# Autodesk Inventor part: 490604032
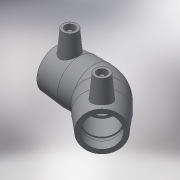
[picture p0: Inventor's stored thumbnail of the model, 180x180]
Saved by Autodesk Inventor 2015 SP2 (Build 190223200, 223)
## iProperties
Created: 2017-06
Part Number: 490604032
Material: Generic
Description: PLASSON 45° ELBOW 32
Document SubType Name: Modeling
Designer: KIM
Mass: 55.0731 g
Surface Area: 148.067 cm^2
Volume: 55.0731 cm^3
Density: 1 g/cm^3
Appearance: Default
Author: KIM
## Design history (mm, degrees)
derived "490604.ipt"
feature "Solid1::490604.ipt"
tag "TaggingFeature1"
body "Solid1"
other parameters: "d2" = 45, "d4" = 23.75, "d5" = 40.5, "d8" = 168 deg, "d10" = 15.6, "d11" = 5.2, "d14" = 17.6296, "d18" = 32, "d19" = 3.52592, "d20" = 168 deg, "d22" = 41.4, "d23" = 45, "d24" = 40.158, "d29" = 43, "d30" = 15, "d31" = 33.25, "d34" = 5 deg, "d35" = 12, "d39" = 0, "d41" = 4, "d42" = 14, "d43" = 0, "d44" = 9.6, "d45" = 4.8, "d46" = 6, "d47" = 0, "d49" = 32, "d50" = 27.2, "d51" = 15.6, "d52" = 39, "d54" = 135 deg, "d65" = 32, "d67" = 45 deg, "d71" = 135 deg, "d75" = 2.25, "d82" = 45 deg, "d83" = 39, "d84" = 40.5, "d86" = 20.25, "d87" = 135 deg, "d88" = 95, "d90" = 39, "d91" = 0, "d92" = 39, "d93" = 0, "d94" = 135 deg, "d95" = 20.7, "d98" = 95, "d99" = 28.5, "d101" = 3, "d102" = 0, "d103" = 3, "d104" = 0, "d105" = 11.31, "d106" = 2.8275, "d_" = 32, "L_" = 95, "L_1" = 39, "D_" = 45, "A_" = 43, "d_2" = 12
